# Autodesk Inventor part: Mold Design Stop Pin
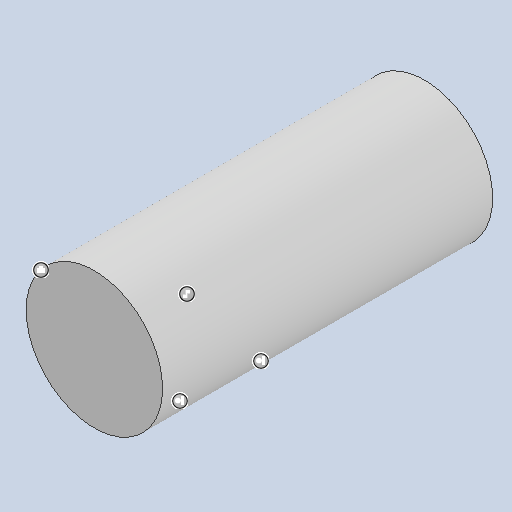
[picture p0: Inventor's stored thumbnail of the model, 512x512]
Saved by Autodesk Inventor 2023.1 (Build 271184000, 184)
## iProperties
Created: 2007-09
Part Number: Mold Design Stop Pin
Document SubType Name: Modeling
Designer: mxwang
Density: 1 g/cm^3
Material: Generic
Appearance: Default
Author: mxwang
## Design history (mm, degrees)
sketch "Sketch1"
  geometry: C1 r 4.132 at (0, 0); 1 further point
  constraints: 1 centre point, 1 coincident
  dimensions: "Diameter" = 8.26421 diameter of C1
extrude "Extrusion1" new body sketch "Sketch1" taper "d2" = 0 deg; stored distance "Height" = 20
body "Solid1"
other parameters: "d3" = 0, "d4" = 0, "d9" = 0, "d10" = 0
